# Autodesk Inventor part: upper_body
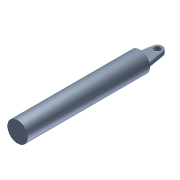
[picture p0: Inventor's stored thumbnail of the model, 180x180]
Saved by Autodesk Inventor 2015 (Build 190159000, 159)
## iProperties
Created: 2020-09
Part Number: upper_body
Material: 一般
Document SubType Name: Modeling
Designer: 徐冠倫
Mass: 4830.06 g
Surface Area: 2213.09 cm^2
Volume: 4830.06 cm^3
Density: 1 g/cm^3
Appearance: 預設
Author: 徐冠倫
Author: IANNIAN
Title: D:\Desktop\OCW-Computer-Aided Engineering Drawing\OCW_Topic 06：組合圖與機構模擬(進階)\6-1_Flexibility\Mechanical Gripper(piston)\Mechanical Gripper(STP)\cylinder1.stp
Creation Date: 2020-09-04
Sending System: Autodesk Inventor 2020
Preprocessor: ST-DEVELOPER v18
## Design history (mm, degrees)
node "upper_body1"
body "Solid1"
node "Base1"
